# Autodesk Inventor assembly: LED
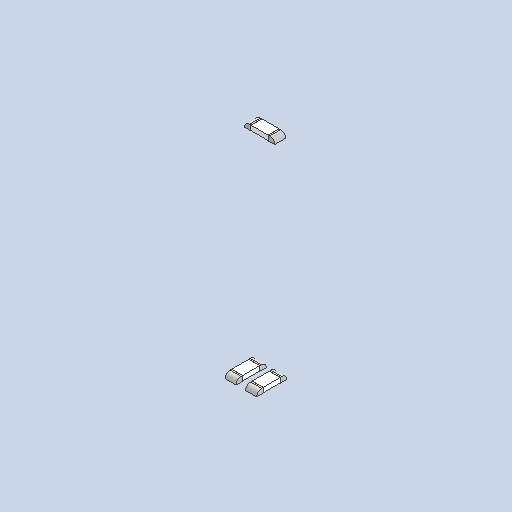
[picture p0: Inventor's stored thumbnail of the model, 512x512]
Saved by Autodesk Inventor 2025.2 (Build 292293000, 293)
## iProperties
Created: 2025-04
Part Number: LED
Description: PART--DESC
Document SubType Name: Assembly
Designer: BennF
Author: BennF
Revision Number: NONE
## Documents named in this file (2)
- C:\Users\BennF\Nextcloud\Benutzer\CNC JarBeRi\existing parts\Electronics\RepRap A4988 Shied (USE WITHOUT ARDUINO)\reprap-a4988-1.snapshot.1\RepRap\RepRap\LED.iam
- C:\Users\BennF\Nextcloud\Benutzer\CNC JarBeRi\existing parts\Electronics\RepRap A4988 Shied (USE WITHOUT ARDUINO)\reprap-a4988-1.snapshot.1\RepRap\RepRap\LED2.ipt
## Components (3 placed, 1 different names)
1. LED2
2. LED2:1
3. LED2:2
